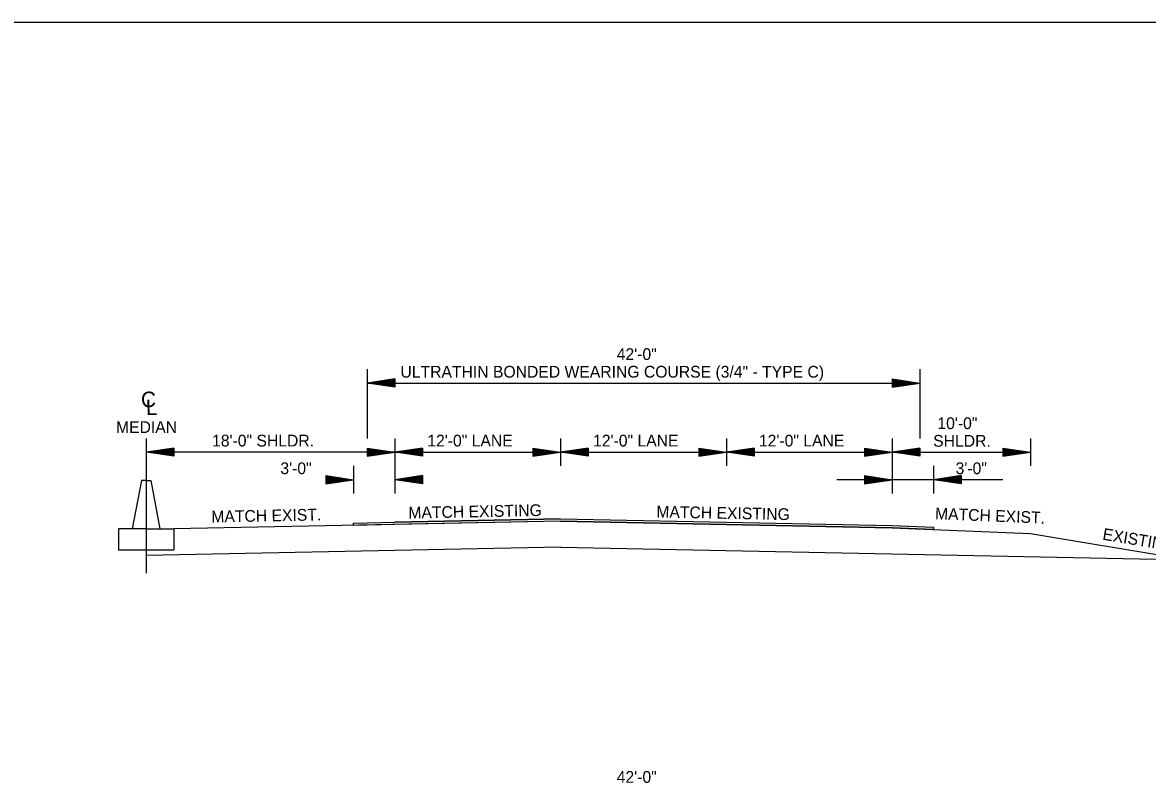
# Model space of a CAD drawing. Extents: x 2261938 to 2263136, y -3124572 to -3124216.
# Drawn here: x 2262179.8 to 2262261.2, y -3124501.3 to -3124446.1 of the extents above; entities that cross this region are included whole.
import ezdxf

# ---------------------------------------------------------------- set-up
doc = ezdxf.new("R2010")
doc.units = 0
for name, color, linetype in [('DSN_DRFT_Common-Annotations', 7, 'Continuous'), ('DSN_DRFT_Common-Line', 7, 'Continuous'), ('DSN_DRFT_Dimension', 7, 'Continuous')]:
    doc.layers.add(name, color=color, linetype=linetype)

msp = doc.modelspace()

# ---------------------------------------------------------------- linework, layer by layer
at = {"layer": 'DSN_DRFT_Common-Line'}
for p, q in [((2262204.758, -3124471.201), (2262204.758, -3124476.201)), ((2262244.758, -3124471.201), (2262244.758, -3124476.201)), ((2262188.758, -3124476.201), (2262188.758, -3124485.95)), ((2262206.758, -3124476.201), (2262206.758, -3124480.201)), ((2262218.758, -3124476.201), (2262218.758, -3124478.201)), ((2262230.758, -3124476.201), (2262230.758, -3124478.201)), ((2262242.758, -3124476.201), (2262242.758, -3124480.201)), ((2262252.758, -3124476.201), (2262252.758, -3124478.201)), ((2262203.758, -3124478.201), (2262203.758, -3124480.201)), ((2262206.758, -3124478.201), (2262206.758, -3124480.201)), ((2262245.758, -3124478.201), (2262245.758, -3124480.201)), ((2262188.425, -3124479.261), (2262187.758, -3124482.761)), ((2262188.758, -3124479.261), (2262188.425, -3124479.261)), ((2262188.758, -3124479.261), (2262189.092, -3124479.261)), ((2262189.092, -3124479.261), (2262189.758, -3124482.761)), ((2262218.758, -3124482.201), (2262190.758, -3124482.761)), ((2262218.758, -3124482.034), (2262206.758, -3124482.274)), ((2262218.758, -3124482.034), (2262242.758, -3124482.514)), ((2262218.758, -3124482.201), (2262242.758, -3124482.681)), ((2262186.758, -3124482.761), (2262186.758, -3124484.261)), ((2262188.758, -3124482.761), (2262186.758, -3124482.761)), ((2262188.758, -3124482.761), (2262190.758, -3124482.761)), ((2262190.758, -3124482.761), (2262190.758, -3124484.261)), ((2262242.758, -3124482.681), (2262252.758, -3124483.081)), ((2262252.758, -3124483.081), (2262272.758, -3124486.414)), ((2262186.758, -3124484.261), (2262190.758, -3124484.261)), ((2262218.758, -3124484.076), (2262188.758, -3124484.676)), ((2262218.758, -3124484.076), (2262264.179, -3124484.984))]:
    msp.add_line(p, q, dxfattribs=at)
for points in [[(2262153.708, -3124446.104), (2262153.708, -3124556.104), (2262323.708, -3124556.104), (2262323.708, -3124446.104)], [(2262242.758, -3124482.681), (2262218.758, -3124482.201), (2262206.758, -3124482.441), (2262203.758, -3124482.501), (2262203.758, -3124482.334), (2262206.758, -3124482.274), (2262218.758, -3124482.034), (2262242.758, -3124482.514), (2262245.758, -3124482.634), (2262245.758, -3124482.801)]]:
    msp.add_lwpolyline(points, close=True, dxfattribs=at)
at = {"layer": 'DSN_DRFT_Dimension'}
for p, q in [((2262206.758, -3124471.901), (2262204.758, -3124472.201)), ((2262206.758, -3124472.501), (2262204.758, -3124472.201)), ((2262204.758, -3124472.201), (2262242.758, -3124472.201)), ((2262206.758, -3124471.951), (2262205.092, -3124472.201)), ((2262206.758, -3124472.451), (2262205.092, -3124472.201)), ((2262206.758, -3124472.002), (2262205.436, -3124472.201)), ((2262206.758, -3124472.4), (2262205.436, -3124472.201)), ((2262206.758, -3124472.052), (2262205.769, -3124472.201)), ((2262206.758, -3124472.35), (2262205.769, -3124472.201)), ((2262206.758, -3124472.104), (2262206.108, -3124472.201)), ((2262206.758, -3124472.299), (2262206.108, -3124472.201)), ((2262206.758, -3124472.154), (2262206.442, -3124472.201)), ((2262206.758, -3124472.248), (2262206.442, -3124472.201)), ((2262206.758, -3124471.901), (2262206.758, -3124472.501)), ((2262242.758, -3124471.901), (2262244.758, -3124472.201)), ((2262242.758, -3124471.901), (2262242.758, -3124472.501)), ((2262242.758, -3124471.951), (2262244.424, -3124472.201)), ((2262242.758, -3124472.002), (2262244.08, -3124472.201)), ((2262242.758, -3124472.052), (2262243.747, -3124472.201)), ((2262242.758, -3124472.104), (2262243.408, -3124472.201)), ((2262242.758, -3124472.154), (2262243.074, -3124472.201)), ((2262242.758, -3124472.501), (2262244.758, -3124472.201)), ((2262242.758, -3124472.299), (2262243.408, -3124472.201)), ((2262242.758, -3124472.4), (2262244.08, -3124472.201)), ((2262242.758, -3124472.451), (2262244.424, -3124472.201)), ((2262242.758, -3124472.35), (2262243.747, -3124472.201)), ((2262242.758, -3124472.248), (2262243.074, -3124472.201)), ((2262190.758, -3124476.901), (2262188.758, -3124477.201)), ((2262206.758, -3124477.201), (2262188.758, -3124477.201)), ((2262190.758, -3124477.501), (2262188.758, -3124477.201)), ((2262190.758, -3124476.951), (2262189.092, -3124477.201)), ((2262190.758, -3124477.451), (2262189.092, -3124477.201)), ((2262190.758, -3124477.002), (2262189.436, -3124477.201)), ((2262190.758, -3124477.4), (2262189.436, -3124477.201)), ((2262190.758, -3124477.052), (2262189.769, -3124477.201)), ((2262190.758, -3124477.35), (2262189.769, -3124477.201)), ((2262190.758, -3124477.104), (2262190.108, -3124477.201)), ((2262190.758, -3124477.299), (2262190.108, -3124477.201)), ((2262190.758, -3124477.154), (2262190.442, -3124477.201)), ((2262190.758, -3124477.248), (2262190.442, -3124477.201)), ((2262190.758, -3124476.901), (2262190.758, -3124477.501)), ((2262204.758, -3124476.901), (2262206.758, -3124477.201)), ((2262204.758, -3124476.901), (2262204.758, -3124477.501)), ((2262204.758, -3124476.951), (2262206.424, -3124477.201)), ((2262204.758, -3124477.002), (2262206.08, -3124477.201)), ((2262204.758, -3124477.052), (2262205.747, -3124477.201)), ((2262204.758, -3124477.104), (2262205.408, -3124477.201)), ((2262204.758, -3124477.154), (2262205.074, -3124477.201)), ((2262204.758, -3124477.501), (2262206.758, -3124477.201)), ((2262204.758, -3124477.299), (2262205.408, -3124477.201)), ((2262204.758, -3124477.4), (2262206.08, -3124477.201)), ((2262204.758, -3124477.451), (2262206.424, -3124477.201)), ((2262204.758, -3124477.35), (2262205.747, -3124477.201)), ((2262204.758, -3124477.248), (2262205.074, -3124477.201)), ((2262208.758, -3124476.901), (2262206.758, -3124477.201)), ((2262206.758, -3124477.201), (2262218.758, -3124477.201)), ((2262208.758, -3124477.501), (2262206.758, -3124477.201)), ((2262208.758, -3124476.951), (2262207.092, -3124477.201)), ((2262208.758, -3124477.451), (2262207.092, -3124477.201)), ((2262208.758, -3124477.002), (2262207.436, -3124477.201)), ((2262208.758, -3124477.4), (2262207.436, -3124477.201)), ((2262208.758, -3124477.052), (2262207.769, -3124477.201)), ((2262208.758, -3124477.35), (2262207.769, -3124477.201)), ((2262208.758, -3124477.104), (2262208.108, -3124477.201)), ((2262208.758, -3124477.299), (2262208.108, -3124477.201)), ((2262208.758, -3124477.154), (2262208.442, -3124477.201)), ((2262208.758, -3124477.248), (2262208.442, -3124477.201)), ((2262208.758, -3124476.901), (2262208.758, -3124477.501)), ((2262216.758, -3124476.901), (2262218.758, -3124477.201)), ((2262216.758, -3124476.901), (2262216.758, -3124477.501)), ((2262216.758, -3124476.951), (2262218.424, -3124477.201)), ((2262216.758, -3124477.002), (2262218.08, -3124477.201)), ((2262216.758, -3124477.052), (2262217.747, -3124477.201)), ((2262216.758, -3124477.104), (2262217.408, -3124477.201)), ((2262216.758, -3124477.154), (2262217.074, -3124477.201)), ((2262216.758, -3124477.501), (2262218.758, -3124477.201)), ((2262216.758, -3124477.299), (2262217.408, -3124477.201)), ((2262216.758, -3124477.4), (2262218.08, -3124477.201)), ((2262216.758, -3124477.451), (2262218.424, -3124477.201)), ((2262216.758, -3124477.35), (2262217.747, -3124477.201)), ((2262216.758, -3124477.248), (2262217.074, -3124477.201)), ((2262220.758, -3124476.901), (2262218.758, -3124477.201)), ((2262218.758, -3124477.201), (2262230.758, -3124477.201)), ((2262220.758, -3124477.501), (2262218.758, -3124477.201)), ((2262220.758, -3124476.951), (2262219.092, -3124477.201)), ((2262220.758, -3124477.451), (2262219.092, -3124477.201)), ((2262220.758, -3124477.002), (2262219.436, -3124477.201)), ((2262220.758, -3124477.4), (2262219.436, -3124477.201)), ((2262220.758, -3124477.052), (2262219.769, -3124477.201)), ((2262220.758, -3124477.35), (2262219.769, -3124477.201)), ((2262220.758, -3124477.104), (2262220.108, -3124477.201)), ((2262220.758, -3124477.299), (2262220.108, -3124477.201)), ((2262220.758, -3124477.154), (2262220.442, -3124477.201)), ((2262220.758, -3124477.248), (2262220.442, -3124477.201)), ((2262220.758, -3124476.901), (2262220.758, -3124477.501)), ((2262228.758, -3124476.901), (2262230.758, -3124477.201)), ((2262228.758, -3124476.901), (2262228.758, -3124477.501)), ((2262228.758, -3124476.951), (2262230.424, -3124477.201)), ((2262228.758, -3124477.002), (2262230.08, -3124477.201)), ((2262228.758, -3124477.052), (2262229.747, -3124477.201)), ((2262228.758, -3124477.104), (2262229.408, -3124477.201)), ((2262228.758, -3124477.154), (2262229.074, -3124477.201)), ((2262228.758, -3124477.501), (2262230.758, -3124477.201)), ((2262228.758, -3124477.299), (2262229.408, -3124477.201)), ((2262228.758, -3124477.4), (2262230.08, -3124477.201)), ((2262228.758, -3124477.451), (2262230.424, -3124477.201)), ((2262228.758, -3124477.35), (2262229.747, -3124477.201)), ((2262228.758, -3124477.248), (2262229.074, -3124477.201)), ((2262232.758, -3124476.901), (2262230.758, -3124477.201)), ((2262230.758, -3124477.201), (2262242.758, -3124477.201)), ((2262232.758, -3124477.501), (2262230.758, -3124477.201)), ((2262232.758, -3124476.951), (2262231.092, -3124477.201)), ((2262232.758, -3124477.451), (2262231.092, -3124477.201)), ((2262232.758, -3124477.002), (2262231.436, -3124477.201)), ((2262232.758, -3124477.4), (2262231.436, -3124477.201)), ((2262232.758, -3124477.052), (2262231.769, -3124477.201)), ((2262232.758, -3124477.35), (2262231.769, -3124477.201)), ((2262232.758, -3124477.104), (2262232.108, -3124477.201)), ((2262232.758, -3124477.299), (2262232.108, -3124477.201)), ((2262232.758, -3124477.154), (2262232.442, -3124477.201)), ((2262232.758, -3124477.248), (2262232.442, -3124477.201)), ((2262232.758, -3124476.901), (2262232.758, -3124477.501)), ((2262240.758, -3124476.901), (2262242.758, -3124477.201)), ((2262240.758, -3124476.901), (2262240.758, -3124477.501)), ((2262240.758, -3124476.951), (2262242.424, -3124477.201)), ((2262240.758, -3124477.002), (2262242.08, -3124477.201)), ((2262240.758, -3124477.052), (2262241.747, -3124477.201)), ((2262240.758, -3124477.104), (2262241.408, -3124477.201)), ((2262240.758, -3124477.154), (2262241.074, -3124477.201)), ((2262240.758, -3124477.501), (2262242.758, -3124477.201)), ((2262240.758, -3124477.299), (2262241.408, -3124477.201)), ((2262240.758, -3124477.4), (2262242.08, -3124477.201)), ((2262240.758, -3124477.451), (2262242.424, -3124477.201)), ((2262240.758, -3124477.35), (2262241.747, -3124477.201)), ((2262240.758, -3124477.248), (2262241.074, -3124477.201)), ((2262244.758, -3124476.901), (2262242.758, -3124477.201)), ((2262242.758, -3124477.201), (2262252.758, -3124477.201)), ((2262244.758, -3124477.501), (2262242.758, -3124477.201)), ((2262244.758, -3124476.951), (2262243.092, -3124477.201)), ((2262244.758, -3124477.451), (2262243.092, -3124477.201)), ((2262244.758, -3124477.002), (2262243.436, -3124477.201)), ((2262244.758, -3124477.4), (2262243.436, -3124477.201)), ((2262244.758, -3124477.052), (2262243.769, -3124477.201)), ((2262244.758, -3124477.35), (2262243.769, -3124477.201)), ((2262244.758, -3124477.104), (2262244.108, -3124477.201)), ((2262244.758, -3124477.299), (2262244.108, -3124477.201)), ((2262244.758, -3124477.154), (2262244.442, -3124477.201)), ((2262244.758, -3124477.248), (2262244.442, -3124477.201)), ((2262244.758, -3124476.901), (2262244.758, -3124477.501)), ((2262250.758, -3124476.901), (2262252.758, -3124477.201)), ((2262250.758, -3124476.901), (2262250.758, -3124477.501)), ((2262250.758, -3124476.951), (2262252.424, -3124477.201)), ((2262250.758, -3124477.002), (2262252.08, -3124477.201)), ((2262250.758, -3124477.052), (2262251.747, -3124477.201)), ((2262250.758, -3124477.104), (2262251.408, -3124477.201)), ((2262250.758, -3124477.154), (2262251.074, -3124477.201)), ((2262250.758, -3124477.501), (2262252.758, -3124477.201)), ((2262250.758, -3124477.299), (2262251.408, -3124477.201)), ((2262250.758, -3124477.4), (2262252.08, -3124477.201)), ((2262250.758, -3124477.451), (2262252.424, -3124477.201)), ((2262250.758, -3124477.35), (2262251.747, -3124477.201)), ((2262250.758, -3124477.248), (2262251.074, -3124477.201)), ((2262201.758, -3124478.901), (2262203.758, -3124479.201)), ((2262201.758, -3124478.901), (2262201.758, -3124479.501)), ((2262201.758, -3124478.951), (2262203.424, -3124479.201)), ((2262208.758, -3124478.901), (2262206.758, -3124479.201)), ((2262208.758, -3124478.951), (2262207.092, -3124479.201)), ((2262208.758, -3124478.901), (2262208.758, -3124479.501)), ((2262240.758, -3124478.901), (2262242.758, -3124479.201)), ((2262240.758, -3124478.901), (2262240.758, -3124479.501)), ((2262240.758, -3124478.951), (2262242.424, -3124479.201)), ((2262247.758, -3124478.901), (2262245.758, -3124479.201)), ((2262247.758, -3124478.951), (2262246.092, -3124479.201)), ((2262247.758, -3124478.901), (2262247.758, -3124479.501)), ((2262201.758, -3124479.002), (2262203.08, -3124479.201)), ((2262201.758, -3124479.052), (2262202.747, -3124479.201)), ((2262201.758, -3124479.104), (2262202.408, -3124479.201)), ((2262201.758, -3124479.154), (2262202.074, -3124479.201)), ((2262201.758, -3124479.501), (2262203.758, -3124479.201)), ((2262201.758, -3124479.299), (2262202.408, -3124479.201)), ((2262201.758, -3124479.4), (2262203.08, -3124479.201)), ((2262201.758, -3124479.451), (2262203.424, -3124479.201)), ((2262201.758, -3124479.35), (2262202.747, -3124479.201)), ((2262201.758, -3124479.248), (2262202.074, -3124479.201)), ((2262208.758, -3124479.501), (2262206.758, -3124479.201)), ((2262208.758, -3124479.451), (2262207.092, -3124479.201)), ((2262208.758, -3124479.002), (2262207.436, -3124479.201)), ((2262208.758, -3124479.4), (2262207.436, -3124479.201)), ((2262208.758, -3124479.052), (2262207.769, -3124479.201)), ((2262208.758, -3124479.35), (2262207.769, -3124479.201)), ((2262208.758, -3124479.104), (2262208.108, -3124479.201)), ((2262208.758, -3124479.299), (2262208.108, -3124479.201)), ((2262208.758, -3124479.154), (2262208.442, -3124479.201)), ((2262208.758, -3124479.248), (2262208.442, -3124479.201)), ((2262250.758, -3124479.201), (2262238.758, -3124479.201)), ((2262240.758, -3124479.002), (2262242.08, -3124479.201)), ((2262240.758, -3124479.052), (2262241.747, -3124479.201)), ((2262240.758, -3124479.104), (2262241.408, -3124479.201)), ((2262240.758, -3124479.154), (2262241.074, -3124479.201)), ((2262240.758, -3124479.501), (2262242.758, -3124479.201)), ((2262240.758, -3124479.299), (2262241.408, -3124479.201)), ((2262240.758, -3124479.4), (2262242.08, -3124479.201)), ((2262240.758, -3124479.451), (2262242.424, -3124479.201)), ((2262240.758, -3124479.35), (2262241.747, -3124479.201)), ((2262240.758, -3124479.248), (2262241.074, -3124479.201)), ((2262247.758, -3124479.501), (2262245.758, -3124479.201)), ((2262247.758, -3124479.451), (2262246.092, -3124479.201)), ((2262247.758, -3124479.002), (2262246.436, -3124479.201)), ((2262247.758, -3124479.4), (2262246.436, -3124479.201)), ((2262247.758, -3124479.052), (2262246.769, -3124479.201)), ((2262247.758, -3124479.35), (2262246.769, -3124479.201)), ((2262247.758, -3124479.104), (2262247.108, -3124479.201)), ((2262247.758, -3124479.299), (2262247.108, -3124479.201)), ((2262247.758, -3124479.154), (2262247.442, -3124479.201)), ((2262247.758, -3124479.248), (2262247.442, -3124479.201))]:
    msp.add_line(p, q, dxfattribs=at)

# ---------------------------------------------------------------- texts
at = {"layer": 'DSN_DRFT_Common-Annotations'}
for s, p in [('42\'-0"', (2262222.821, -3124470.531)), ('ULTRATHIN BONDED WEARING COURSE (3/4" - TYPE C)', (2262207.169, -3124471.806)), ('10\'-0"', (2262246.028, -3124475.531)), ('MEDIAN', (2262186.582, -3124475.812)), ('18\'-0" SHLDR.', (2262193.535, -3124476.791)), ('12\'-0" LANE', (2262209.111, -3124476.791)), ('12\'-0" LANE', (2262221.111, -3124476.791)), ('12\'-0" LANE', (2262233.111, -3124476.791)), ('SHLDR.', (2262245.724, -3124476.806)), (' 3\'-0"', (2262198.161, -3124478.791)), (' 3\'-0"', (2262247.031, -3124478.791)), ('42\'-0"', (2262222.821, -3124501.131))]:
    msp.add_text(s, height=0.85, dxfattribs=at).set_placement(p)
for s, height, rotation, p in [('C', 1.124, 1.14576, (2262188.401, -3124473.956)), ('L', 1.124, 1.14576, (2262188.751, -3124474.521)), ('MATCH EXIST.', 0.85, 1.14576, (2262193.488, -3124482.296)), ('MATCH EXISTING', 0.85, 1.14576, (2262207.748, -3124482.011)), ('MATCH EXISTING', 0.85, 358.85424, (2262225.68, -3124481.929)), ('MATCH EXIST.', 0.85, 357.70939, (2262245.845, -3124482.056)), ('EXISTING SLOPE', 0.85, 350.538, (2262257.94, -3124483.529))]:
    msp.add_text(s, height=height, rotation=rotation, dxfattribs=at).set_placement(p)

doc.saveas('drawing.dxf')
